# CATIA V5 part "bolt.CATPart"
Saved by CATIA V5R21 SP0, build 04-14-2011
Part number: bolt
Bounding box of the stored display mesh (mm): x -17.5 to 17.5, y -20.207 to 20.207, z 0 to 105
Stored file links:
  F:\catia_prac\bolt.CATPart
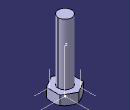
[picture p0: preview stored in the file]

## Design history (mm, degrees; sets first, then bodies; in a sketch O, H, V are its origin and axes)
AxisSystem1: origin (0, 0, 0), X (1, 0, 0), Y (0, 1, 0), Z (0, 0, 1)
Body1 (main body)
  Sketch1 on XY plane of AxisSystem1, origin (0, 0, 0), H (1, 0, 0), V (0, 1, 0)
    point P1 (17.5, -10.1036)
    point P2 (17.5, 10.1036)
    point P3 (0, 20.2073)
    point P4 (-17.5, 10.1036)
    point P5 (-17.5, -10.1036)
    point P6 (0, -20.2073)
    point P7 (17.5, 0)
    line L1 (17.5, -10.1036) -> (17.5, 10.1036)
    line L2 (17.5, 10.1036) -> (0, 20.2073)
    line L3 (0, 20.2073) -> (-17.5, 10.1036)
    line L4 (-17.5, 10.1036) -> (-17.5, -10.1036)
    line L5 (-17.5, -10.1036) -> (0, -20.2073)
    line L6 (0, -20.2073) -> (17.5, -10.1036)
    construction line L7 (0, 0) -> (17.5, 0)
    construction circle A1 centre (0, 0) radius 20.2073
    construction arc A2 centre (-17.5, -10.1036) radius 20.2073 from (-17.5, 10.1036) to (0, -20.2073) cw
    construction arc A3 centre (17.5, 10.1036) radius 20.2073 from (0, 20.2073) to (17.5, -10.1036) ccw
    distance L1 L4 = 35
    horizontal: L7 H
    coincidence: A1 P1, A1 P2, A1 P3, A1 P4, A1 P5, A1 P6, A2 O, A3 O
    midpoint: P7 L1
  Pad1: profile Sketch1, direction (0, 0, 1), length 15
  Sketch2 on end face of Pad1, origin (0, 0, 15), H (1, 0, 0), V (0, 1, 0)
    circle A1 centre (0, 0) radius 10
    radius A1 = 10
  Pad2: profile Sketch2, direction (0, 0, 1), length 90
  Sketch3 on yz-plane, origin (0, 0, 0), H (0, 1, 0), V (0, 0, 1)
    point P1 (17.5, 0)
    line L1 (17.5, 0) -> (23.9624, 0)
    line L2 (23.9624, 0) -> (23.9624, 3.7311)
    line L3 (23.9624, 3.7311) -> (17.5, 0)
    angle L1 L3 = 30
    distance O P1 = 17.5
    coincidence: P1 H
    horizontal: L1 H
    vertical: L2 V
  Groove1: profile Sketch3, axis axis of face of Pad2 from Sketch2.A1, angle 360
